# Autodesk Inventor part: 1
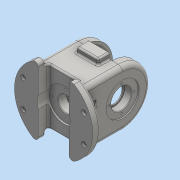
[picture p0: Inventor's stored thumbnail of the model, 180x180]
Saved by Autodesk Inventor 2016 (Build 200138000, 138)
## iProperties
Created: 2024-08
Part Number: 1
Material: 알루미늄 6061
Document SubType Name: Modeling
Designer: pc-2
Density: 2.7 g/cm^3
Appearance: 기본값
Mass: 1199.05 g
Surface Area: 1051.82 cm^2
Volume: 444.094 cm^3
Author: pc-2
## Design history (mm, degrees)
sketch "스케치1"
  geometry: C1 r 71 at (0, 0); 1 further point
  constraints: 1 centre point, 1 coincident
  dimensions: "d0" = 142 diameter of C1
extrude "돌출1" new body sketch "스케치1" distance "d1" = 13; taper "d2" = 0 deg
sketch "스케치2"
  geometry: L1 (81, 51)-(13, 51); L2 (13, 51)-(13, -51); L3 (13, -71)-(13, 71) reference; L4 (81, -51)-(13, -51); L5 (81, 0)-(13, 0); L6 (0, 71)-(0, -71) reference; A1 r 51 centre (81, 0) between (81, 51) and (81, -51); 1 further point
  constraints: 8 end point, 2 horizontal, 2 point on circle, 2 point on line, 2 tangent, 1 centre point, 1 midpoint, 1 perpendicular
  dimensions: "d3" = 102 diameter of A1; "d4" = 81 distance from line of L6 L5.start
extrude "돌출2" join sketch "스케치2" stored distance "d5" = 88; taper "d6" = 0 deg
sketch "스케치3"
  geometry: L1 (-28, 0)-(28, 0); L2 (28, 0)-(28, 19); L3 (28, 19)-(-28, 19); L4 (-28, 19)-(-28, 0); L5 (0, 19)-(0, 0)
  constraints: 10 end point, 2 parallel, 1 horizontal, 1 midpoint, 1 perpendicular, 1 vertical
  dimensions: "d7" = 56 distance of L2.end L3.end; "d8" = 19 distance of L1.end L2.end
extrude "돌출3" cut sketch "스케치3" stored distance "d9" = 256; taper "d10" = 0 deg
sketch "스케치4"
  geometry: L1 (0, 51)-(88, 51) reference; L2 (0, 0)-(88, 0) reference; L3 (19, 51)-(69, 51); L4 (69, 51)-(69, 0); L5 (69, 0)-(19, 0); L6 (19, 0)-(19, 51); L7 (44, 0)-(44, -81)
  constraints: 10 end point, 2 parallel, 2 point on line, 1 horizontal, 1 midpoint, 1 perpendicular, 1 vertical
  dimensions: "d11" = 50 distance between parallel lines of L6 L4
extrude "돌출4" cut sketch "스케치4" distance "d12" = 574.25; taper "d13" = 0 deg
sketch "스케치5"
  geometry: L1 (81, 51)-(81, -51) reference; L2 (81, 46)-(40, 46); L3 (40, 46)-(40, -46); L4 (40, -46)-(81, -46); L5 (81, -46)-(81, 46); L6 (0, -65.246)-(0, 65.246) reference; A1 r 51 centre (81, 0) between (81, -51) and (81, 51) reference; A2 r 46 centre (81, 0) between (40, -20.857) and (40, 20.857); 1 further point
  constraints: 8 end point, 3 point on circle, 3 point on line, 2 parallel, 1 centre point, 1 coincident, 1 horizontal, 1 perpendicular, 1 tangent
  dimensions: "d14" = 5 radial gap between concentric circles of A1 A2; "d15" = 40 distance between parallel lines of L6 L3
extrude "돌출5" cut sketch "스케치5" stored distance "d16" = 78; taper "d17" = 0 deg
sketch "스케치6"
  geometry: L1 (0, 0)-(-30, 0); L2 (-30, 0)-(-30, 22); L3 (-30, 22)-(0, 22); L4 (0, 22)-(0, 0); L5 (0, 22)-(-14, 22); L6 (-14, 22)-(-14, 37); L7 (-14, 37)-(0, 37); L8 (0, 37)-(0, 22); L9 (-39, 40)-(39, 40) reference; L10 (0, 37)-(-11, 37); L11 (-11, 37)-(-11, 40); L12 (-11, 40)-(0, 40); L13 (0, 40)-(0, 37)
  constraints: 24 end point, 6 parallel, 3 horizontal, 3 perpendicular, 1 point on line
  dimensions: "d18" = 30 distance of L2.end L3.end; "d19" = 22 distance of L1.end L2.end; "d20" = 15 distance of L5.end L6.end; "d21" = 14 distance of L6.end L7.end; "d22" = 11 distance between parallel lines of L13 L11
revolve "회전1" sketch "스케치6" stored, may be unused: angle "d23" = 90 deg
sketch "스케치7"
  geometry: A1 r 23 centre (0, 0) between (0, 23) and (-23, 0); 3 further points
  constraints: 4 point on circle, 1 centre point, 1 coincident
  dimensions: "d24" = 46 diameter of A1
hole "구멍1" sketch "스케치7" at (0, 23), (-23, 0), (0, -23), (23, 0) diameter "d25" = 3.242; stored, may be unused: countersink angle "d29" = 90 deg, drill point angle "d31" = 118 deg; dims "d26" = 8, "d27" = 4, "d28" = 2, "d30" = 10
sketch "스케치8"
  geometry: L1 (-39, 127)-(-39, 81) reference; L2 (-39, 114.5)-(-27, 102.5); L3 (-27, 102.5)-(-27, 81); L4 (-39, 81)-(-25, 81) reference; L5 (-27, 81)-(-39, 81); 1 further point
  constraints: 6 end point, 1 collinear, 1 parallel, 1 point on line
  dimensions: "d32" = 33.5 distance from line of L4 L2.start; "d33" = 12 horizontal distance of L2.start L2.end; "d34" = 45 deg angle of L1 L2
revolve "회전2" sketch "스케치8" stored, may be unused: angle "d35" = 90 deg
sketch "스케치9"
  geometry: C1 r 30 at (0, 81); A1 r 51 centre (0, 81) between (51, 81) and (-51, 81) reference; 1 further point
  constraints: 1 centre point, 1 coincident
  dimensions: "d36" = 60 diameter of C1
extrude "돌출6" cut sketch "스케치9" distance "d37" = 2; taper "d38" = 0 deg
sketch "스케치10"
  geometry: C1 r 30 at (0, 0) reference; C2 r 18.5 at (0, 0); 1 further point
  constraints: 1 centre point, 1 coincident
  dimensions: "d39" = 37 diameter of C2
extrude "돌출7" cut sketch "스케치10" distance "d40" = 13; taper "d41" = 0 deg
sketch "스케치11"
  geometry: C1 r 18.5 at (0, 0) reference; C2 r 16 at (0, 0); 1 further point
  constraints: 1 centre point, 1 coincident
  dimensions: "d42" = 32 diameter of C2
extrude "돌출8" cut sketch "스케치11" distance "d43" = 13.25; taper "d44" = 0 deg
sketch "스케치12"
  geometry: C1 r 16 at (0, 0) reference; A1 r 23 centre (0, 0) between (0, 23) and (-23, 0); 3 further points
  constraints: 4 point on circle, 1 centre point, 1 coincident
  dimensions: "d45" = 46 diameter of A1
hole "구멍2" sketch "스케치12" at (0, 23), (-23, 0), (0, -23), (23, 0) diameter "d46" = 3.242; stored, may be unused: countersink angle "d50" = 90 deg, drill point angle "d52" = 118 deg; dims "d47" = 8, "d48" = 4, "d49" = 2, "d51" = 10
sketch "스케치13"
  geometry: L1 (0, 0)-(50, 0) reference; L2 (5, 0)-(45, 0); L3 (45, 0)-(45, 10); L4 (45, 10)-(5, 10); L5 (5, 10)-(5, 0); L6 (50, -102)-(0, -102) reference; L7 (5, -102)-(45, -102); L8 (45, -102)-(45, -112); L9 (45, -112)-(5, -112); L10 (5, -112)-(5, -102); L11 (5, -102)-(45, -102); L12 (45, -102)-(45, 0); L13 (45, 0)-(5, 0); L14 (5, 0)-(5, -102); L15 (25, -51)-(25, 0)
  constraints: 26 end point, 6 parallel, 3 horizontal, 3 perpendicular, 2 point on line, 1 midpoint, 1 vertical
  dimensions: "d53" = 40 distance of L8.end L9.end; "d54" = 61 distance from line of L15.start L4; "d55" = 61 distance from line of L9 L15.start
extrude "돌출9" join sketch "스케치13" distance "d56" = 20; taper "d57" = 0 deg
sketch "스케치14"
  geometry: L1 (12, 8)-(38, 8); L2 (38, 8)-(38, -100); L3 (38, -100)-(12, -100); L4 (12, -100)-(12, 8); L5 (12, 8)-(38, -100); L6 (38, 8)-(12, -100); 5 further points
  constraints: 12 end point, 4 coincident, 2 midpoint, 2 parallel, 1 horizontal, 1 perpendicular
  dimensions: "d58" = 26 distance of L2.end L3.end; "d59" = 108 distance of L1.end L2.end
hole "구멍3" sketch "스케치14" at (12, 8), (12, -100), (38, -100), (38, 8) diameter "d60" = 3.242; stored, may be unused: countersink angle "d64" = 90 deg, drill point angle "d66" = 118 deg; dims "d61" = 8, "d62" = 4, "d63" = 2, "d65" = 10
fillet "모깎기1" dims "d67" = 0.3
fillet "모깎기2" dims "d68" = 8
fillet "모깎기3" dims "d69" = 6
sketch "스케치15"
  geometry: L1 (-55, 25)-(55, 25); L2 (55, 25)-(55, -25); L3 (55, -25)-(-55, -25); L4 (-55, -25)-(-55, 25); L5 (-55, 25)-(55, -25); L6 (55, 25)-(-55, -25); 5 further points
  constraints: 12 end point, 4 coincident, 2 midpoint, 2 parallel, 1 horizontal, 1 perpendicular
  dimensions: "d70" = 50 distance of L1.end L2.end; "d71" = 110 distance of L1.start L1.end
hole "구멍4" sketch "스케치15" at (-55, 25), (-55, -25), (55, -25), (55, 25) diameter "d72" = 9; stored, may be unused: countersink angle "d76" = 90 deg, drill point angle "d78" = 118 deg; dims "d73" = 8, "d74" = 15, "d75" = 8.8, "d77" = 10
sketch "스케치16"
  geometry: L1 (-26.595, 33.618)-(26.595, 33.618); L2 (26.595, 33.618)-(26.595, 26.382); L3 (26.595, 26.382)-(-26.595, 26.382); L4 (-26.595, 26.382)-(-26.595, 33.618); L5 (0, 26.382)-(0, 0); L6 (26.595, 30)-(-26.595, 30); L7 (-60.512, 0)-(60.512, 0) reference
  constraints: 4 end point, 3 midpoint, 1 horizontal, 1 vertical, 2 other
  dimensions: "d79" = 30 distance between parallel lines of L7 L6
extrude "돌출10" cut sketch "스케치16" distance "d80" = 0.5; taper "d81" = 0 deg
chamfer "모따기1" distance "d82" = 1; stored, may be unused: second distance "d83" = 2, angle "d84" = 45 deg
fillet "모깎기4" dims "d85" = 3
fillet "모깎기5" dims "d86" = 3
fillet "모깎기6" dims "d87" = 3
fillet "모깎기7" dims "d88" = 3
fillet "모깎기8" dims "d89" = 3
fillet "모깎기9" dims "d90" = 3
fillet "모깎기10" dims "d91" = 3
fillet "모깎기11" dims "d92" = 3
node "솔리드1"
mirror "대칭1"
